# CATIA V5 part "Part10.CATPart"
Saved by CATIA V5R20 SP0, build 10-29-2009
Part number: 3JT7.5X2X11.5
Revision: ANY
Definition: UNKNOWN
Nomenclature: 3JT7.5X2X11.5
Source: Unknown
Bounding box of the stored display mesh (mm): x -5.75 to 5.75, y -5.75 to 5.75, z -1 to 1
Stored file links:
  C:\Users\Utente\Desktop\IO LAVORO\3D X SITO CF\CUMSA\3D files PW\pw060630\pw060630_injection\Part10.CATPart
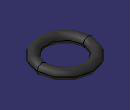
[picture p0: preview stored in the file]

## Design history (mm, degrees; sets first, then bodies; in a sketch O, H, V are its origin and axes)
Body1 "Revolución1" (main body)
  Solid1: solid without history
